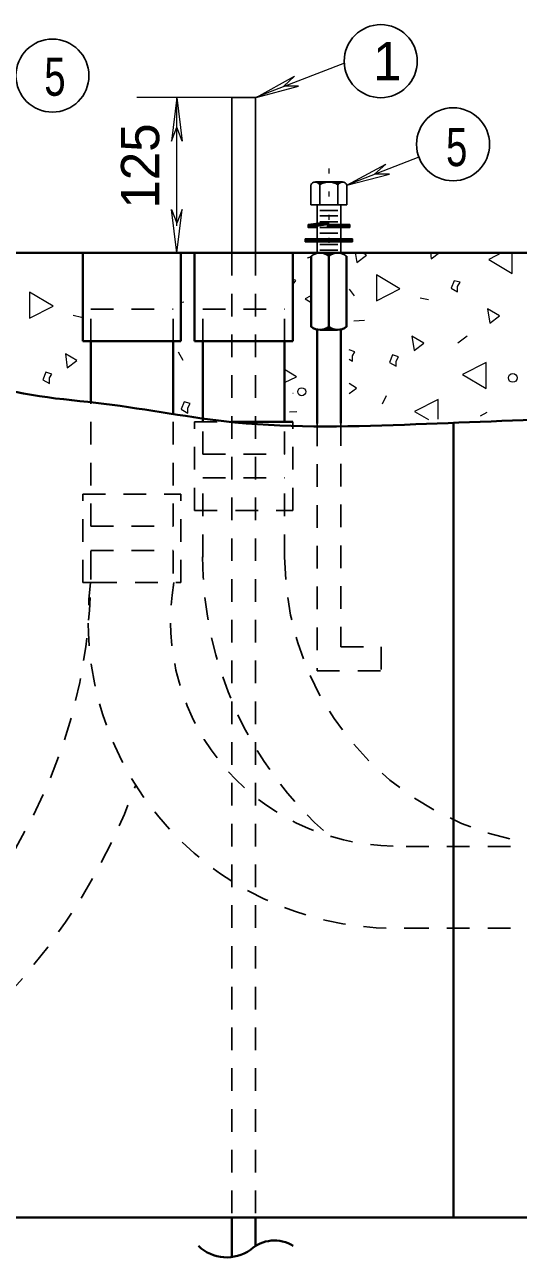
# Model space of a CAD drawing. Extents: x 312583 to 312854, y 144419 to 144597.
# Drawn here: x 312738.15 to 312747.96, y 144437.25 to 144461.74 of the extents above; entities that cross this region are included whole.
import ezdxf

# ---------------------------------------------------------------- set-up
doc = ezdxf.new("R2010")
doc.units = 0
doc.header["$LTSCALE"] = 0.3
doc.linetypes.add('DOTTED', pattern=[1.5, 0.3, -1.2])
doc.linetypes.add('SHORT_DASHED', pattern=[2.7, 1.5, -1.2])
doc.layers.add('1', color=7, linetype='Continuous', lineweight=25)
doc.layers.add('2', color=7, linetype='Continuous', lineweight=13)

msp = doc.modelspace()

# ---------------------------------------------------------------- linework, layer by layer
at = {"layer": '1', "linetype": 'DOTTED', "lineweight": 13}
msp.add_line((312744.1953, 144458.8804), (312744.1953, 144457.2014), dxfattribs=at)
at = {"layer": '1'}
for p, q in [((312743.835, 144458.5507), (312743.835, 144458.1597)), ((312743.927, 144458.612), (312744.4636, 144458.612)), ((312744.0113, 144458.5507), (312744.0113, 144458.1597)), ((312744.3716, 144458.5507), (312744.3716, 144458.1597)), ((312744.548, 144458.5507), (312744.548, 144458.1597)), ((312743.835, 144458.1597), (312744.548, 144458.1597)), ((312743.9576, 144458.1597), (312743.9576, 144457.2014)), ((312744.433, 144458.1597), (312744.433, 144457.2014)), ((312744.0113, 144458.0447), (312744.3716, 144458.0447)), ((312744.0113, 144457.9374), (312744.3716, 144457.9374)), ((312743.7813, 144457.7687), (312743.7813, 144457.7074)), ((312744.0113, 144457.8224), (312744.3716, 144457.8224)), ((312744.0113, 144457.7074), (312744.3716, 144457.7074)), ((312744.157, 144457.7074), (312744.6093, 144457.7074)), ((312744.1723, 144457.7687), (312744.6093, 144457.7687)), ((312744.6093, 144457.7687), (312744.6093, 144457.7074)), ((312743.72, 144457.485), (312744.663, 144457.485)), ((312743.72, 144457.485), (312743.72, 144457.4237)), ((312743.72, 144457.4697), (312744.663, 144457.4697)), ((312743.72, 144457.4544), (312744.663, 144457.4544)), ((312743.72, 144457.439), (312744.663, 144457.439)), ((312743.72, 144457.4237), (312744.663, 144457.4237)), ((312744.0113, 144457.5924), (312744.3716, 144457.5924)), ((312744.663, 144457.485), (312744.663, 144457.4237)), ((312743.9576, 144457.2014), (312744.433, 144457.2014)), ((312744.0113, 144457.37), (312744.3716, 144457.37)), ((312744.0113, 144457.255), (312744.3716, 144457.255)), ((312744.019, 144457.2014), (312744.364, 144457.2014))]:
    msp.add_line(p, q, dxfattribs=at)
at = {"layer": '1', "lineweight": 40}
for p, q in [((312734.5276, 144457.2014), (312777.9746, 144457.2014)), ((312739.304, 144455.4457), (312739.304, 144457.2014)), ((312741.2513, 144455.4457), (312741.2513, 144457.2014)), ((312741.5273, 144455.4457), (312741.5273, 144457.2014)), ((312743.4746, 144455.4457), (312743.4746, 144457.2014)), ((312744.1953, 144457.2014), (312744.1953, 144455.6757)), ((312743.8426, 144457.14), (312743.8426, 144455.737)), ((312744.5403, 144457.14), (312744.5403, 144455.737)), ((312739.304, 144455.4457), (312741.2513, 144455.4457)), ((312739.465, 144454.2497), (312739.465, 144455.4457)), ((312741.098, 144454.012), (312741.098, 144455.4457)), ((312741.5273, 144455.4457), (312743.4746, 144455.4457)), ((312743.3136, 144453.8434), (312743.3136, 144455.4457)), ((312743.9576, 144455.6757), (312743.9576, 144453.8127)), ((312744.019, 144455.6757), (312744.364, 144455.6757)), ((312744.433, 144455.6757), (312744.433, 144453.8204)), ((312742.248, 144453.8434), (312743.4746, 144453.8434)), ((312746.6716, 144453.828), (312746.6716, 144438.0347)), ((312733.8913, 144438.0347), (312778.611, 144438.0347)), ((312742.2633, 144438.0347), (312742.2633, 144437.2515)), ((312742.7386, 144438.0347), (312742.7386, 144437.4751))]:
    msp.add_line(p, q, dxfattribs=at)
at = {"layer": '1', "linetype": 'SHORT_DASHED'}
for p, q in [((312742.2633, 144457.2014), (312742.2633, 144438.0347)), ((312742.7386, 144457.2014), (312742.7386, 144438.0347)), ((312739.465, 144456.082), (312741.098, 144456.082)), ((312739.465, 144455.4457), (312739.465, 144456.082)), ((312741.098, 144455.4457), (312741.098, 144456.082)), ((312741.6883, 144456.082), (312743.3136, 144456.082)), ((312741.6883, 144455.4457), (312741.6883, 144456.082)), ((312743.3136, 144455.4457), (312743.3136, 144456.082)), ((312739.465, 144451.7734), (312739.465, 144454.2497)), ((312741.098, 144451.7734), (312741.098, 144454.012)), ((312741.5273, 144452.0877), (312741.5273, 144453.8434)), ((312741.5273, 144453.8434), (312742.248, 144453.8434)), ((312741.6883, 144453.207), (312741.6883, 144453.8434)), ((312743.3136, 144453.207), (312743.3136, 144453.8434)), ((312743.9576, 144453.8127), (312743.9576, 144448.8984)), ((312744.433, 144453.8204), (312744.433, 144449.3737)), ((312741.6883, 144453.207), (312743.3136, 144453.207)), ((312741.6883, 144452.7317), (312743.3136, 144452.7317)), ((312741.6883, 144451.16), (312741.6883, 144452.7317)), ((312743.3136, 144451.16), (312743.3136, 144452.7317)), ((312739.304, 144450.654), (312739.304, 144452.4097)), ((312739.304, 144452.4097), (312741.2513, 144452.4097)), ((312741.5273, 144452.0877), (312743.4746, 144452.0877)), ((312739.465, 144451.7734), (312741.098, 144451.7734)), ((312739.465, 144451.2904), (312741.098, 144451.2904)), ((312739.465, 144450.8304), (312739.465, 144451.2904)), ((312741.098, 144450.8304), (312741.098, 144451.2904)), ((312743.9576, 144448.8984), (312745.2303, 144448.8984)), ((312745.7286, 144445.41), (312752.4676, 144445.41)), ((312745.7286, 144443.7847), (312752.4676, 144443.7847))]:
    msp.add_line(p, q, dxfattribs=at)
at = {"layer": '1'}
for points in [[(312743.95, 144458.612), (312744.1493, 144458.612), (312744.111, 144458.6044), (312744.088, 144458.5967), (312744.0496, 144458.5814), (312744.0113, 144458.5584), (312744.0036, 144458.5814), (312743.9883, 144458.589), (312743.9576, 144458.6044), (312744.134, 144458.6044), (312744.0803, 144458.5967), (312744.042, 144458.5814), (312744.019, 144458.566), (312743.9883, 144458.589), (312743.9653, 144458.6044), (312744.111, 144458.6044), (312744.0573, 144458.589), (312744.019, 144458.566), (312743.9806, 144458.6044), (312744.0956, 144458.6044), (312744.0113, 144458.5737), (312743.9806, 144458.5967), (312744.0803, 144458.6044), (312744.0113, 144458.5737), (312743.996, 144458.5967), (312744.065, 144458.5967), (312744.0113, 144458.5814), (312744.0036, 144458.5967), (312744.0496, 144458.5967), (312744.019, 144458.5814), (312744.0113, 144458.5967), (312744.0266, 144458.589), (312744.019, 144458.589)], [(312744.4406, 144458.612), (312744.2413, 144458.612), (312744.272, 144458.6044), (312744.295, 144458.5967), (312744.3333, 144458.5814), (312744.3716, 144458.5584), (312744.387, 144458.5814), (312744.4023, 144458.589), (312744.433, 144458.6044), (312744.2566, 144458.6044), (312744.3026, 144458.5967), (312744.341, 144458.5814), (312744.3716, 144458.566), (312744.3946, 144458.589), (312744.4176, 144458.6044), (312744.2796, 144458.6044), (312744.3256, 144458.589), (312744.3716, 144458.566), (312744.41, 144458.6044), (312744.295, 144458.6044), (312744.3716, 144458.5737), (312744.4023, 144458.5967), (312744.3026, 144458.6044), (312744.3716, 144458.5737), (312744.3946, 144458.5967), (312744.318, 144458.5967), (312744.3716, 144458.5814), (312744.387, 144458.5967), (312744.341, 144458.5967), (312744.3716, 144458.5814), (312744.3793, 144458.5967), (312744.3563, 144458.589), (312744.3716, 144458.589)], [(312743.7813, 144457.7687), (312744.1953, 144457.8224), (312744.157, 144457.7074)], [(312743.9576, 144457.7074), (312743.7813, 144457.715), (312743.789, 144457.761), (312744.18, 144457.8147), (312744.1646, 144457.7687), (312743.95, 144457.738), (312743.95, 144457.715), (312743.789, 144457.7227), (312743.789, 144457.7534), (312744.1723, 144457.807), (312744.1646, 144457.7764), (312743.9423, 144457.738), (312743.9346, 144457.7227), (312743.7966, 144457.7304), (312743.7966, 144457.7457), (312744.157, 144457.7994), (312744.157, 144457.784), (312743.9423, 144457.7457), (312743.927, 144457.738), (312743.8886, 144457.7304), (312743.8043, 144457.738), (312744.1493, 144457.7917), (312743.858, 144457.738)], [(312744.1723, 144457.7687), (312743.7813, 144457.7074), (312743.9576, 144457.7074)], [(312744.1646, 144457.715), (312744.6016, 144457.715), (312744.6016, 144457.761), (312744.18, 144457.7534), (312744.1723, 144457.7227), (312744.594, 144457.7227), (312744.594, 144457.7534), (312744.1876, 144457.7457), (312744.18, 144457.7304), (312744.5863, 144457.7304), (312744.5786, 144457.738), (312744.5786, 144457.7457), (312744.1876, 144457.7457), (312744.1876, 144457.738), (312744.5786, 144457.738)], [(312744.065, 144457.2014), (312744.3256, 144457.2014), (312744.295, 144457.1937), (312744.2643, 144457.186), (312744.2413, 144457.1707), (312744.2183, 144457.163), (312744.1953, 144457.1477), (312744.1953, 144457.14), (312744.1416, 144457.1707), (312744.1033, 144457.1937), (312744.0803, 144457.1937), (312744.3026, 144457.2014), (312744.2873, 144457.1937), (312744.2643, 144457.1937), (312744.2413, 144457.1784), (312744.2106, 144457.163), (312744.203, 144457.1554), (312744.1953, 144457.1477), (312744.1493, 144457.1784), (312744.1033, 144457.1937), (312744.272, 144457.1937), (312744.2336, 144457.1784), (312744.1953, 144457.1554), (312744.1186, 144457.1937), (312744.2566, 144457.1937), (312744.1953, 144457.1554), (312744.134, 144457.186), (312744.2413, 144457.1937), (312744.1953, 144457.163), (312744.157, 144457.186), (312744.226, 144457.186), (312744.1953, 144457.1784), (312744.157, 144457.1784), (312744.18, 144457.1707), (312744.1876, 144457.186), (312744.1876, 144457.163), (312744.2106, 144457.1784), (312744.2183, 144457.1784), (312744.226, 144457.186)]]:
    msp.add_lwpolyline(points, dxfattribs=at)
at = {"layer": '1', "lineweight": 40}
for points in [[(312744.065, 144455.6757), (312744.3256, 144455.6757), (312744.295, 144455.6834), (312744.2643, 144455.691), (312744.2413, 144455.6987), (312744.2183, 144455.714), (312744.1953, 144455.7294), (312744.1953, 144455.7294), (312744.1416, 144455.6987), (312744.1033, 144455.6834), (312744.0803, 144455.6757), (312744.3026, 144455.6757), (312744.2873, 144455.6834), (312744.2643, 144455.6834), (312744.2413, 144455.691), (312744.2106, 144455.7064), (312744.203, 144455.7217), (312744.1953, 144455.7294), (312744.1493, 144455.6987), (312744.1033, 144455.6834), (312744.272, 144455.6834), (312744.2336, 144455.691), (312744.1953, 144455.7217), (312744.1186, 144455.6834), (312744.2566, 144455.6834), (312744.1953, 144455.7217), (312744.134, 144455.6834), (312744.2413, 144455.6834), (312744.1953, 144455.714), (312744.157, 144455.691), (312744.226, 144455.691), (312744.1953, 144455.6987), (312744.157, 144455.691), (312744.18, 144455.7064), (312744.1876, 144455.691), (312744.1876, 144455.714), (312744.2106, 144455.6987), (312744.2183, 144455.6987), (312744.226, 144455.691)], [(312741.6883, 144453.8434), (312741.6883, 144453.9277), (312741.6883, 144455.4457)]]:
    msp.add_lwpolyline(points, dxfattribs=at)
at = {"layer": '1', "linetype": 'SHORT_DASHED'}
for points in [[(312743.4746, 144452.0877), (312743.4746, 144453.8204), (312743.4746, 144453.8434)], [(312739.304, 144450.654), (312739.534, 144450.654), (312741.2513, 144450.654), (312741.2513, 144452.4097)], [(312744.433, 144449.3737), (312745.2303, 144449.3737), (312745.2303, 144448.8984)]]:
    msp.add_lwpolyline(points, dxfattribs=at)
at = {"layer": '1'}
for centre, radius, start, end in [((312743.9241, 144458.5118), 0.0993, 25.60064, 154.39936), ((312744.1928, 144458.2985), 0.3126, 55.04559, 124.95441), ((312744.4614, 144458.5118), 0.0993, 25.60064, 154.39936), ((312744.0179, 144456.9293), 0.272, 50.00693, 129.99306), ((312744.3675, 144456.9293), 0.272, 50.00694, 129.99307)]:
    msp.add_arc(centre, radius, start, end, dxfattribs=at)
at = {"layer": '1', "lineweight": 40}
for centre, radius, start, end in [((312744.0179, 144455.9466), 0.272, 230.00694, 309.99307), ((312744.3675, 144455.9466), 0.272, 230.00693, 309.99306), ((312743.1104, 144436.8667), 0.713, 58.11032, 131.90694), ((312742.1641, 144438.048), 0.8027, 225.84295, 305.84934)]:
    msp.add_arc(centre, radius, start, end, dxfattribs=at)
at = {"layer": '1', "linetype": 'SHORT_DASHED'}
for centre, radius, start, end in [((312749.0649, 144451.1639), 7.3792, 180, 228.72648), ((312749.0649, 144451.1639), 5.75, 180, 270), ((312728.7802, 144450.8285), 10.6854, 298.57612, 0), ((312728.7802, 144450.8285), 12.3146, 294.52268, 340.05203)]:
    msp.add_arc(centre, radius, start, end, dxfattribs=at)
at = {"layer": '1', "lineweight": 40}
msp.add_spline([(312749.332, 144453.9354), (312745.9203, 144453.7974), (312742.3246, 144453.8357), (312739.7256, 144454.2037), (312737.1726, 144454.6637), (312735.7696, 144455.691), (312735.5166, 144457.2167)], degree=3, dxfattribs=at)
at = {"layer": '2'}
for p, q in [((312744.502, 144460.9734), (312742.7386, 144460.291)), ((312742.7463, 144460.291), (312743.513, 144460.7127)), ((312743.513, 144460.7127), (312743.2983, 144460.5134)), ((312742.7463, 144460.291), (312743.5896, 144460.5134)), ((312743.5896, 144460.5134), (312743.2983, 144460.5134)), ((312742.616, 144460.291), (312740.3773, 144460.291)), ((312741.1746, 144460.291), (312741.0673, 144459.4247)), ((312741.1746, 144460.291), (312741.282, 144459.4247)), ((312741.1746, 144457.738), (312741.1746, 144460.291)), ((312741.0673, 144459.4247), (312741.1746, 144459.7007)), ((312741.282, 144459.4247), (312741.1746, 144459.7007)), ((312745.9816, 144459.1027), (312744.548, 144458.5507)), ((312744.548, 144458.5507), (312745.3223, 144458.9647)), ((312745.3223, 144458.9647), (312745.1, 144458.7654)), ((312744.548, 144458.5507), (312745.399, 144458.7654)), ((312745.399, 144458.7654), (312745.1, 144458.7654)), ((312741.0673, 144458.0677), (312741.1746, 144457.7917)), ((312741.1746, 144457.2014), (312741.0673, 144458.0677)), ((312741.282, 144458.0677), (312741.1746, 144457.7917)), ((312741.1746, 144457.2014), (312741.282, 144458.0677)), ((312742.8153, 144457.209), (312742.8306, 144457.2014)), ((312743.0913, 144457.2014), (312743.099, 144457.209)), ((312744.7166, 144457.209), (312744.7473, 144457.0097)), ((312746.2116, 144457.209), (312746.227, 144457.0864)), ((312746.227, 144457.0864), (312746.388, 144457.209)), ((312747.837, 144456.795), (312747.837, 144457.209)), ((312744.594, 144456.4807), (312744.6936, 144456.3504)), ((312741.2513, 144456.22), (312741.3126, 144456.2277)), ((312746.0046, 144456.312), (312746.1733, 144456.2737)), ((312739.1123, 144455.967), (312739.281, 144455.9287)), ((312744.686, 144455.852), (312744.9006, 144455.8674)), ((312741.6806, 144455.4457), (312741.6883, 144455.438)), ((312746.94, 144455.5454), (312746.756, 144455.4074)), ((312741.1976, 144455.2387), (312741.2896, 144455.07)), ((312743.4746, 144454.4184), (312743.4823, 144454.4184)), ((312745.33, 144454.3647), (312745.2533, 144454.196)), ((312743.4133, 144454.0427), (312743.559, 144454.0504)), ((312747.2083, 144453.966), (312747.3386, 144454.035))]:
    msp.add_line(p, q, dxfattribs=at)
at = {"layer": '2', "lineweight": 25}
for p, q in [((312742.2633, 144460.291), (312742.7386, 144460.291)), ((312742.2633, 144457.2014), (312742.2633, 144460.291)), ((312742.7386, 144457.2014), (312742.7386, 144460.291)), ((312743.766, 144457.1017), (312743.8196, 144457.117))]:
    msp.add_line(p, q, dxfattribs=at)
at = {"layer": '2'}
for points in [[(312744.7473, 144457.0097), (312744.939, 144457.1554), (312744.847, 144457.209)], [(312747.6376, 144457.209), (312747.3693, 144457.071), (312747.837, 144456.795)], [(312739.304, 144457.025), (312739.2963, 144457.025), (312739.304, 144456.956)], [(312743.4823, 144456.5804), (312743.536, 144456.657), (312743.4746, 144456.68)], [(312743.4746, 144456.4807), (312743.4823, 144456.473), (312743.4823, 144456.5804)], [(312743.8196, 144456.3427), (312743.72, 144456.289), (312743.8196, 144456.2277)], [(312744.663, 144455.1544), (312744.709, 144455.2387), (312744.594, 144455.277)], [(312744.594, 144455.093), (312744.663, 144455.0547), (312744.663, 144455.1544)], [(312743.3136, 144454.6254), (312743.5513, 144454.7404), (312743.3136, 144454.886)], [(312744.594, 144454.4107), (312744.7396, 144454.518), (312744.594, 144454.61)], [(312746.365, 144453.897), (312746.365, 144454.288), (312745.8973, 144454.0504), (312746.1733, 144453.8894)]]:
    msp.add_lwpolyline(points, dxfattribs=at)
for points in [[(312745.1383, 144456.7644), (312745.1383, 144456.2507), (312745.606, 144456.4884)], [(312746.7483, 144456.5344), (312746.802, 144456.6187), (312746.6793, 144456.6494), (312746.6256, 144456.5037), (312746.7483, 144456.427)], [(312738.246, 144456.4194), (312738.246, 144455.9057), (312738.7136, 144456.1434)], [(312747.3923, 144455.806), (312747.584, 144455.9517), (312747.3463, 144456.0897)], [(312745.8896, 144455.2617), (312746.0813, 144455.4074), (312745.8436, 144455.5454)], [(312738.9973, 144454.9167), (312739.189, 144455.0624), (312738.959, 144455.2004)], [(312745.5293, 144455.0547), (312745.5753, 144455.139), (312745.4603, 144455.1774), (312745.399, 144455.024), (312745.5293, 144454.955)], [(312747.3156, 144454.5104), (312747.3156, 144455.024), (312746.848, 144454.7864)], [(312738.6446, 144454.7174), (312738.6906, 144454.794), (312738.568, 144454.8324), (312738.5143, 144454.679), (312738.6446, 144454.61)], [(312741.3893, 144454.127), (312741.4353, 144454.2114), (312741.3203, 144454.242), (312741.259, 144454.0964), (312741.3893, 144454.0197)]]:
    msp.add_lwpolyline(points, close=True, dxfattribs=at)
at = {"layer": '2', "lineweight": 25}
for centre in [(312745.2239, 144461.0123), (312738.7021, 144460.7248), (312746.6601, 144459.3602)]:
    msp.add_circle(centre, 0.7254, dxfattribs=at)
at = {"layer": '2'}
for centre, radius in [((312747.845, 144454.7184), 0.0865), ((312743.6549, 144454.4442), 0.0784)]:
    msp.add_circle(centre, radius, dxfattribs=at)
at = {"layer": '2', "linetype": 'SHORT_DASHED', "lineweight": 25}
for radius, start, end in [(6.1088, 172.82646, 272.66759), (4.4722, 170.17896, 272.66947)]:
    msp.add_arc((312745.5204, 144449.8899), radius, start, end, dxfattribs=at)

# ---------------------------------------------------------------- texts
at = {"layer": '2'}
msp.add_text('1', height=0.76, dxfattribs=at).set_placement((312745.0723, 144460.6318))
at = {"layer": '2', "width": 0.75}
for p in [(312738.5393, 144460.3251), (312746.5204, 144458.927)]:
    msp.add_text('5', height=0.76, dxfattribs=at).set_placement(p)
at = {"layer": '2'}
msp.add_text('125', height=0.76, rotation=90, dxfattribs=at).set_placement((312740.8231, 144458.0805))

doc.saveas('drawing.dxf')
